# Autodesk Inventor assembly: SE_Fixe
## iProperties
Shininess: 64.0
Length Units: 11269
Angle Units: 11279
Time Units: 11290
Mass Units: 11283
Length Display Precision: 3
Angle Display Precision: 2
Compacted: True
Created: 2005-01
Part Number: SE_Fixe
Document SubType Name: Assembly
Designer: MARTY
Density: 0.0
Volumn: 0.0
Area: 0.0
PropertySet Name: Model Information
Control State: 0
Master: False
Checked Out: False
Author: MARTY
